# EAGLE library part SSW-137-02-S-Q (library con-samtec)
THROUGH-HOLE .025" SQ POST SOCKET Source: Samtec SSW.pdf
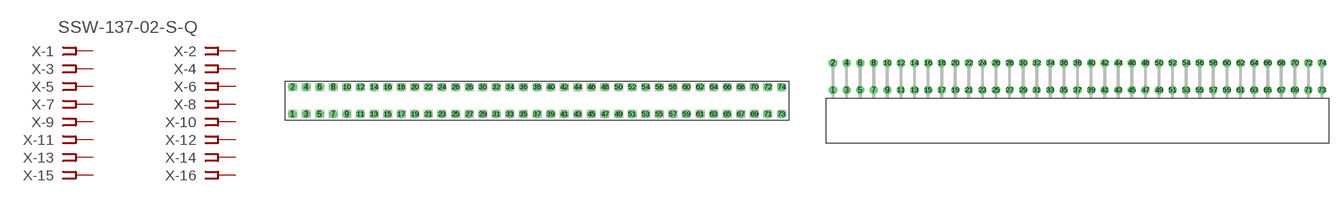
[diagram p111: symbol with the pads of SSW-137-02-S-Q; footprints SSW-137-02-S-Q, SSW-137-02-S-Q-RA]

Designator prefix X; gates -1=FPINV -2=FPIN -3=FPIN -4=FPIN -5=FPIN -6=FPIN -7=FPIN -8=FPIN -9=FPIN -10=FPIN -11=FPIN -12=FPIN -13=FPIN -14=FPIN -15=FPIN -16=FPIN -17=FPIN -18=FPIN -19=FPIN -20=FPIN -21=FPIN -22=FPIN -23=FPIN -24=FPIN -25=FPIN -26=FPIN -27=FPIN -28=FPIN -29=FPIN -30=FPIN -31=FPIN -32=FPIN -33=FPIN -34=FPIN -35=FPIN -36=FPIN -37=FPIN -38=FPIN -39=FPIN -40=FPIN -41=FPIN -42=FPIN -43=FPIN -44=FPIN -45=FPIN -46=FPIN -47=FPIN -48=FPIN -49=FPIN -50=FPIN -51=FPIN -52=FPIN -53=FPIN -54=FPIN -55=FPIN -56=FPIN -57=FPIN -58=FPIN -59=FPIN -60=FPIN -61=FPIN -62=FPIN -63=FPIN -64=FPIN -65=FPIN -66=FPIN -67=FPIN -68=FPIN -69=FPIN -70=FPIN -71=FPIN -72=FPIN -73=FPIN -74=FPIN

## SSW-137-02-S-Q (OC_FARNELL: unknown; OC_NEWARK: unknown)  [SSW-137-02-S-Q]
1  -1:1  pas
2  -2:1  pas
3  -3:1  pas
4  -4:1  pas
5  -5:1  pas
6  -6:1  pas
7  -7:1  pas
8  -8:1  pas
9  -9:1  pas
10  -10:1  pas
11  -11:1  pas
12  -12:1  pas
13  -13:1  pas
14  -14:1  pas
15  -15:1  pas
16  -16:1  pas
17  -17:1  pas
18  -18:1  pas
19  -19:1  pas
20  -20:1  pas
21  -21:1  pas
22  -22:1  pas
23  -23:1  pas
24  -24:1  pas
25  -25:1  pas
26  -26:1  pas
27  -27:1  pas
28  -28:1  pas
29  -29:1  pas
30  -30:1  pas
31  -31:1  pas
32  -32:1  pas
33  -33:1  pas
34  -34:1  pas
35  -35:1  pas
36  -36:1  pas
37  -37:1  pas
38  -38:1  pas
39  -39:1  pas
40  -40:1  pas
41  -41:1  pas
42  -42:1  pas
43  -43:1  pas
44  -44:1  pas
45  -45:1  pas
46  -46:1  pas
47  -47:1  pas
48  -48:1  pas
49  -49:1  pas
50  -50:1  pas
51  -51:1  pas
52  -52:1  pas
53  -53:1  pas
54  -54:1  pas
55  -55:1  pas
56  -56:1  pas
57  -57:1  pas
58  -58:1  pas
59  -59:1  pas
60  -60:1  pas
61  -61:1  pas
62  -62:1  pas
63  -63:1  pas
64  -64:1  pas
65  -65:1  pas
66  -66:1  pas
67  -67:1  pas
68  -68:1  pas
69  -69:1  pas
70  -70:1  pas
71  -71:1  pas
72  -72:1  pas
73  -73:1  pas
74  -74:1  pas

## SSW-137-02-S-QRA (OC_FARNELL: unknown; OC_NEWARK: unknown)  [SSW-137-02-S-Q-RA]
Pads as for SSW-137-02-S-Q

## Footprint SSW-137-02-S-Q (pad centres in mm)
THROUGH-HOLE .025" SQ POST SOCKET Source: Samtec SSW.pdf
drill 1 pad 1.5 octagon: 1 -45.72,-2.54; 2 -45.72,2.54; 3 -43.18,-2.54; 4 -43.18,2.54; 5 -40.64,-2.54; 6 -40.64,2.54; 7 -38.1,-2.54; 8 -38.1,2.54; 9 -35.56,-2.54; 10 -35.56,2.54; 11 -33.02,-2.54; 12 -33.02,2.54; 13 -30.48,-2.54; 14 -30.48,2.54; 15 -27.94,-2.54; 16 -27.94,2.54; 17 -25.4,-2.54; 18 -25.4,2.54; 19 -22.86,-2.54; 20 -22.86,2.54; 21 -20.32,-2.54; 22 -20.32,2.54; 23 -17.78,-2.54; 24 -17.78,2.54; 25 -15.24,-2.54; 26 -15.24,2.54; 27 -12.7,-2.54; 28 -12.7,2.54; 29 -10.16,-2.54; 30 -10.16,2.54; 31 -7.62,-2.54; 32 -7.62,2.54; 33 -5.08,-2.54; 34 -5.08,2.54; 35 -2.54,-2.54; 36 -2.54,2.54; 37 0,-2.54; 38 0,2.54; 39 2.54,-2.54; 40 2.54,2.54; 41 5.08,-2.54; 42 5.08,2.54; 43 7.62,-2.54; 44 7.62,2.54; 45 10.16,-2.54; 46 10.16,2.54; 47 12.7,-2.54; 48 12.7,2.54; 49 15.24,-2.54; 50 15.24,2.54; 51 17.78,-2.54; 52 17.78,2.54; 53 20.32,-2.54; 54 20.32,2.54; 55 22.86,-2.54; 56 22.86,2.54; 57 25.4,-2.54; 58 25.4,2.54; 59 27.94,-2.54; 60 27.94,2.54; 61 30.48,-2.54; 62 30.48,2.54; 63 33.02,-2.54; 64 33.02,2.54; 65 35.56,-2.54; 66 35.56,2.54; 67 38.1,-2.54; 68 38.1,2.54; 69 40.64,-2.54; 70 40.64,2.54; 71 43.18,-2.54; 72 43.18,2.54; 73 45.72,-2.54; 74 45.72,2.54

## Footprint SSW-137-02-S-Q-RA (pad centres in mm)
THROUGH-HOLE .025" SQ POST SOCKET Source: Samtec SSW.pdf
drill 1 pad 1.5 octagon: 1 -45.72,1.524; 2 -45.72,6.604; 3 -43.18,1.524; 4 -43.18,6.604; 5 -40.64,1.524; 6 -40.64,6.604; 7 -38.1,1.524; 8 -38.1,6.604; 9 -35.56,1.524; 10 -35.56,6.604; 11 -33.02,1.524; 12 -33.02,6.604; 13 -30.48,1.524; 14 -30.48,6.604; 15 -27.94,1.524; 16 -27.94,6.604; 17 -25.4,1.524; 18 -25.4,6.604; 19 -22.86,1.524; 20 -22.86,6.604; 21 -20.32,1.524; 22 -20.32,6.604; 23 -17.78,1.524; 24 -17.78,6.604; 25 -15.24,1.524; 26 -15.24,6.604; 27 -12.7,1.524; 28 -12.7,6.604; 29 -10.16,1.524; 30 -10.16,6.604; 31 -7.62,1.524; 32 -7.62,6.604; 33 -5.08,1.524; 34 -5.08,6.604; 35 -2.54,1.524; 36 -2.54,6.604; 37 0,1.524; 38 0,6.604; 39 2.54,1.524; 40 2.54,6.604; 41 5.08,1.524; 42 5.08,6.604; 43 7.62,1.524; 44 7.62,6.604; 45 10.16,1.524; 46 10.16,6.604; 47 12.7,1.524; 48 12.7,6.604; 49 15.24,1.524; 50 15.24,6.604; 51 17.78,1.524; 52 17.78,6.604; 53 20.32,1.524; 54 20.32,6.604; 55 22.86,1.524; 56 22.86,6.604; 57 25.4,1.524; 58 25.4,6.604; 59 27.94,1.524; 60 27.94,6.604; 61 30.48,1.524; 62 30.48,6.604; 63 33.02,1.524; 64 33.02,6.604; 65 35.56,1.524; 66 35.56,6.604; 67 38.1,1.524; 68 38.1,6.604; 69 40.64,1.524; 70 40.64,6.604; 71 43.18,1.524; 72 43.18,6.604; 73 45.72,1.524; 74 45.72,6.604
